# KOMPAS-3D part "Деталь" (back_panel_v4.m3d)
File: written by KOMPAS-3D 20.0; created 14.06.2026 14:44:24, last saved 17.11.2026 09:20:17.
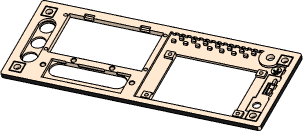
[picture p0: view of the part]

Document properties: Полное имя файла: D:\RicWork\Project-EPS32\box_compas\корпус\back_panel_v4.m3d

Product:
- Part/product: Деталь
    Материал: Фанера, береза,ФСФ ВВ/С ГОСТ 3916.1-2018 (density 760 kg/m3)
    Масса: 0.0215078

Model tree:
1. Эскиз:1
2. Элемент выдавливания:1
     Расстояние 1 = 4
3. Эскиз:5  (with: Элемент выдавливания:1)
4. Элемент выдавливания:5
     Расстояние 2 = 2
5. Эскиз:6  (with: Элемент выдавливания:1, Элемент выдавливания:5)
6. Эскиз:4  (with: Элемент выдавливания:1, Элемент выдавливания:5)
7. Элемент выдавливания:6
     Расстояние 2 = 4
8. Массив по сетке:14  (with: Элемент выдавливания:6, Эскиз:6)  (4 pattern instances)
     Шаг 1 = 196; Угол раствора = -90; Шаг 2 = 60
9. Эскиз:16  (with: Элемент выдавливания:1, Элемент выдавливания:5)
10. Элемент выдавливания:19
     Расстояние 2 = 4
11. Эскиз:17  (with: Элемент выдавливания:1, Элемент выдавливания:19)
12. Элемент выдавливания:23
     Расстояние 2 = 4
13. Эскиз:20  (with: Элемент выдавливания:5, Элемент выдавливания:19)
14. Элемент выдавливания:24
     Расстояние 2 = 1.5
15. Скругление:7  (with: Элемент выдавливания:24)
     Радиус = 3
16. Эскиз:22  (with: Элемент выдавливания:5)
17. Элемент выдавливания:26
     Расстояние 1 = 2
18. Скругление:8  (with: Элемент выдавливания:26)
     Радиус = 0.4
19. Массив по сетке:5  (with: Элемент выдавливания:26, Эскиз:22, Скругление:8, Элемент выдавливания:5)  (5 pattern instances)
     Шаг 1 = 8.25; Угол раствора = 90
20. Эскиз:25  (with: Элемент выдавливания:5)
21. Элемент выдавливания:28
     Расстояние 1 = 2
22. Скругление:10  (with: Элемент выдавливания:28)
     Радиус = 0.4
23. Массив по сетке:7  (with: Элемент выдавливания:28, Эскиз:25, Скругление:10)  (15 pattern instances)
     Шаг 1 = 5; Угол раствора = 90
24. Массив по концентрической сетке:3  (with: Элемент выдавливания:23, Эскиз:17, Элемент выдавливания:19)  (5 pattern instances)
     Шаг 2 = 360
25. Эскиз:29  (with: Элемент выдавливания:5, Элемент выдавливания:1)
26. Элемент выдавливания:36
     Расстояние 2 = 2
27. Смещенная плоскость:1  (with: Элемент выдавливания:1)
     Расстояние = 13.75
28. Эскиз:32  (with: Элемент выдавливания:36)
29. Элемент вращения:3
     Угол 1 = 360
30. Элемент выдавливания:46
     Расстояние 2 = 4
31. Эскиз:2  (with: Элемент выдавливания:1, Элемент выдавливания:46)
32. Элемент выдавливания:2
     Расстояние 2 = 4
33. Массив по сетке:1  (with: Элемент выдавливания:2, Эскиз:2)  (4 pattern instances)
     Шаг 1 = 83; Угол раствора = 90; Шаг 2 = 37
34. Эскиз:39  (with: Элемент выдавливания:1, Элемент выдавливания:46)
35. Элемент выдавливания:48
     Расстояние 2 = 4
36. Массив по сетке:11  (with: Элемент выдавливания:48, Эскиз:39, Элемент выдавливания:1)  (4 pattern instances)
     Шаг 1 = 75.9; Угол раствора = 90; Шаг 2 = 44.2
37. Эскиз:35  (with: Элемент выдавливания:5, Элемент выдавливания:2, Скругление:7, Элемент выдавливания:36, Элемент выдавливания:46, Элемент выдавливания:48)
38. Элемент выдавливания:50
     Расстояние 1 = 2
39. Эскиз:41  (with: Элемент выдавливания:5, Элемент выдавливания:46, Элемент выдавливания:48)
40. Элемент выдавливания:71
     Расстояние 1 = 2
41. Эскиз:46  (with: Элемент выдавливания:5, Элемент выдавливания:28, Элемент выдавливания:1)
42. Элемент выдавливания:59
     Расстояние 1 = 2
43. Массив по сетке:13  (with: Элемент выдавливания:59, Эскиз:46, Элемент выдавливания:1)  (7 pattern instances)
     Шаг 1 = 10; Угол раствора = 90
44. Эскиз:47  (with: Элемент выдавливания:5, Элемент выдавливания:1, Элемент выдавливания:26)
45. Элемент выдавливания:60
     Расстояние 2 = 0.5
46. Эскиз:49  (with: Элемент выдавливания:1, Элемент выдавливания:6, Элемент выдавливания:19, Элемент выдавливания:23, Элемент выдавливания:36, Элемент выдавливания:46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)
47. Эскиз:53  (with: Элемент выдавливания:1)
48. Элемент выдавливания:64
     Расстояние 2 = 0.2
49. Массив по сетке:15  (with: Элемент выдавливания:64, Эскиз:53)  (4 pattern instances)
     Шаг 1 = 196; Угол раствора = -90; Шаг 2 = 60
50. Фаска:2  (with: Элемент выдавливания:50)
     Угол = 45; Длина 1 = 0.4; Длина 2 = 0.4
51. Эскиз:56  (with: Элемент выдавливания:50)
52. Элемент выдавливания:72
     Расстояние 2 = 2
53. Скругление:19  (with: Элемент выдавливания:72)
     Радиус = 1
54. Эскиз:54  (with: Элемент выдавливания:1, Элемент выдавливания:50, Элемент выдавливания:64, Фаска:2)
55. Элемент выдавливания:74
     Расстояние 2 = 2.5
56. Скругление:17  (with: Элемент выдавливания:1)
     Радиус = 1
57. Скругление:18  (with: Элемент выдавливания:1)
     Радиус = 2
58. Эскиз:58  (with: Элемент выдавливания:60)
59. Элемент выдавливания:75
     Расстояние 1 = 2.5
60. Эскиз:59  (with: Элемент выдавливания:60)
61. Элемент выдавливания:76
     Расстояние 1 = 2
62. Эскиз:60  (with: Элемент выдавливания:50)
63. Эскиз:61  (with: Элемент выдавливания:50)
64. Элемент выдавливания:77
     Расстояние 2 = 2.5
65. Элемент выдавливания:78  (labels: Фанера, береза,ФСФ ВВ/С ГОСТ 3916.1-2018)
